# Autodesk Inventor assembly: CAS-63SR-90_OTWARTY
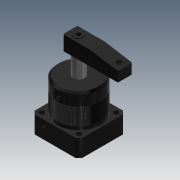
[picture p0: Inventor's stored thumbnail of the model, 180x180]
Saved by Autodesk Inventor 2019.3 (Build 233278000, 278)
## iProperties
Created: 2009-09
Part Number: CAS-63SR-90_OTWARTY
Material: Ogólny
Document SubType Name: Assembly
Designer: CADENGINEERING4
Sending System: PRO/ENGINEER BY PARAMETRIC TECHNOLOGY CORPORATION, 2007170
Preprocessor: PRO/ENGINEER BY PARAMETRIC TECHNOLOGY CORPORATION, 2007170
Title: CAS-63S_ASM
Author: Administrator
Revision Number: 1LAST_VERSION
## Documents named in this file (7)
- D:\Vault_2016\Projekty\STRONA\Pneumatic\Line ; Pipe connecct - type\cas-63s_asm\CAS-63SR-90_OTWARTY.iam
- D:\Vault_2016\Projekty\STRONA\Pneumatic\Line ; Pipe connecct - type\cas-63s_asm\CAS-63BT.ipt
- D:\Vault_2016\Projekty\STRONA\Pneumatic\Line ; Pipe connecct - type\cas-63s_asm\CAS-63SHSG.ipt
- D:\Vault_2016\Projekty\STRONA\Pneumatic\Line ; Pipe connecct - type\cas-63s_asm\CAS-63HG.ipt
- D:\Vault_2016\Projekty\STRONA\Pneumatic\Line ; Pipe connecct - type\cas-63s_asm\M4.ipt
- D:\Vault_2016\Projekty\STRONA\Pneumatic\Line ; Pipe connecct - type\cas-63s_asm\CAS-63SYB.ipt
- D:\Vault_2016\Projekty\STRONA\Pneumatic\Line ; Pipe connecct - type\cas-63s_asm\M10LC.ipt
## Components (11 placed, 11 different names)
1. CAS-63BT_0 — Kątowe:1
2. CAS-63SHSG_1 — Zestawiające:2
3. CAS-63HG_2
4. M4_3
5. M4_4
6. M4_5
7. M4_6
8. M4_7
9. M4_8
10. CAS-63SYB_9 — Zestawiające:1, Kątowe:1, Zestawiające:2
11. M10LC_10 — Zestawiające:1
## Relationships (3: Mate 2, Angle 1)
- Zestawiające:1 [Mate]: CAS-63SYB_9 ↔ M10LC_10
- Kątowe:1 [Angle]: CAS-63BT_0 ↔ CAS-63SYB_9
- Zestawiające:2 [Mate]: CAS-63SHSG_1 ↔ CAS-63SYB_9
